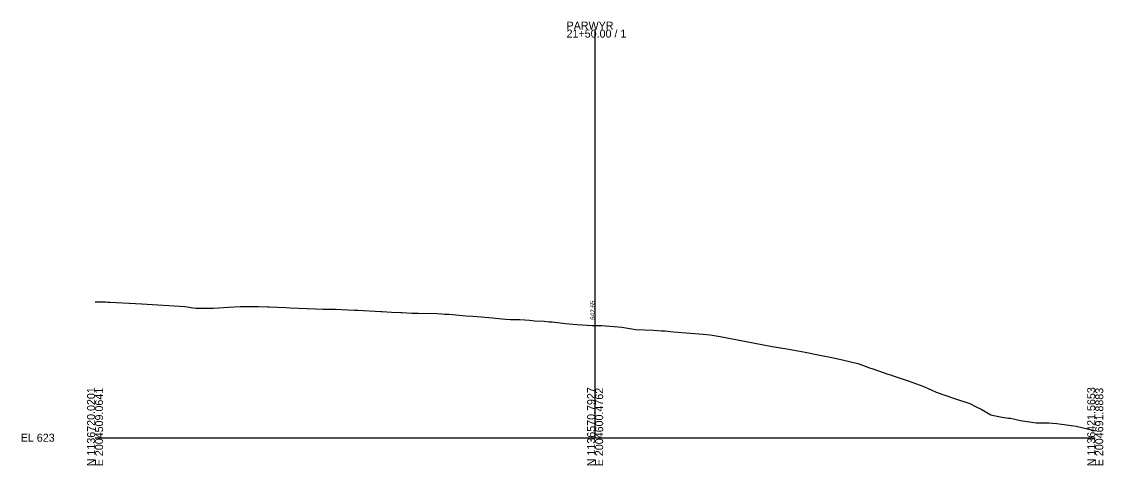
# Model space of a CAD drawing. Extents: x -2173 to 2007764, y -181 to 1138563.
# Drawn here: x -1982.6 to -1604.1, y 2490.3 to 2645.7 of the extents above; entities that cross this region are included whole.
import ezdxf

# ---------------------------------------------------------------- set-up
doc = ezdxf.new("R2010")
doc.units = 0
for name, color, linetype in [('Default', 7, 'Continuous'), ('RD_PD_Final_TrvlWay', 7, 'Continuous'), ('RD_PD_MedBWall', 7, 'Continuous'), ('RD_XS_TX_Elev_EX', 7, 'Continuous')]:
    doc.layers.add(name, color=color, linetype=linetype)

msp = doc.modelspace()

# ---------------------------------------------------------------- linework, layer by layer
at = {"layer": 'RD_PD_Final_TrvlWay'}
msp.add_lwpolyline([(-1956.9, 2547.65), (-1956.16, 2547.63), (-1955.73, 2547.62), (-1955.22, 2547.6), (-1954.01, 2547.58), (-1953.3, 2547.56), (-1952.51, 2547.53), (-1951.6, 2547.49), (-1949.34, 2547.37), (-1944.98, 2547.14), (-1940.57, 2546.89), (-1925.43, 2546), (-1924.65, 2545.88), (-1922.54, 2545.55), (-1921.46, 2545.42), (-1920.51, 2545.35), (-1920.1, 2545.33), (-1919.22, 2545.32), (-1916.69, 2545.36), (-1915.46, 2545.4), (-1910.17, 2545.71), (-1906.12, 2545.91), (-1904.25, 2545.96), (-1902.61, 2545.98), (-1900.04, 2545.92), (-1899.74, 2545.94), (-1896.59, 2545.85), (-1896.01, 2545.83), (-1890.16, 2545.61), (-1888.65, 2545.55), (-1882.65, 2545.3), (-1879.71, 2545.17), (-1877.1, 2545.08), (-1874.89, 2545.03), (-1872.77, 2544.97), (-1868.27, 2544.81), (-1866.16, 2544.72), (-1864.91, 2544.67), (-1856.9, 2544.22), (-1856.46, 2544.2), (-1853.18, 2544), (-1849.91, 2543.84), (-1849.46, 2543.82), (-1846.1, 2543.66), (-1843.81, 2543.59), (-1837.14, 2543.45), (-1835.61, 2543.35), (-1834.49, 2543.26), (-1833, 2543.22), (-1827.1, 2542.74), (-1824.63, 2542.55), (-1817.68, 2542), (-1816.75, 2541.9), (-1813.31, 2541.57), (-1811.51, 2541.44), (-1810.44, 2541.4), (-1808.92, 2541.43), (-1808.2, 2541.35), (-1806.54, 2541.29), (-1804.88, 2541.14), (-1802.96, 2540.96), (-1799.76, 2540.8), (-1797.99, 2540.6), (-1796.97, 2540.54), (-1792.28, 2540), (-1789.61, 2539.76), (-1788.16, 2539.63), (-1782.93, 2539.25), (-1782.61, 2539.28), (-1781.9, 2539.29), (-1781.48, 2539.3), (-1780.64, 2539.28), (-1779.57, 2539.25), (-1778.27, 2539.19), (-1776.78, 2539.1), (-1775.21, 2538.99), (-1773.79, 2538.86), (-1772.54, 2538.7), (-1769.02, 2538.1), (-1768.32, 2538), (-1767.62, 2537.96), (-1761.49, 2537.64), (-1758.73, 2537.47), (-1757.53, 2537.38), (-1754.48, 2537.13), (-1744.06, 2536.23), (-1741.71, 2536), (-1738.15, 2535.42), (-1719.92, 2532), (-1714.88, 2531.08), (-1708.46, 2530), (-1703.26, 2528.92), (-1698.51, 2528), (-1694.84, 2527.18), (-1689.96, 2526), (-1687.11, 2524.99), (-1686.2, 2524.62), (-1684.37, 2524), (-1679.48, 2522.3), (-1678.59, 2522), (-1677.57, 2521.68), (-1672.4, 2519.93), (-1667.21, 2518), (-1664.54, 2516.94), (-1662.57, 2516), (-1656.16, 2513.72), (-1650.81, 2512), (-1648.61, 2510.87), (-1646.83, 2510), (-1643.41, 2508), (-1641.77, 2507.61), (-1639.53, 2507.22), (-1637.23, 2506.89), (-1636.56, 2506.79), (-1633.1, 2506), (-1627.58, 2505.26), (-1626.71, 2505.19), (-1625.89, 2505.18), (-1623.14, 2505.17), (-1621.91, 2505.11), (-1620.36, 2504.99), (-1619.56, 2504.89), (-1613.61, 2504), (-1609.09, 2502.94), (-1606.9, 2502.36)], dxfattribs=at)
at = {"layer": 'RD_PD_MedBWall'}
for p, q in [((-1781.9, 2500), (-1781.9, 2642.94)), ((-1956.9, 2500), (-1781.9, 2500)), ((-1781.9, 2500), (-1606.9, 2500))]:
    msp.add_line(p, q, dxfattribs=at)

# ---------------------------------------------------------------- texts
at = {"layer": 'Default'}
msp.add_text('-', height=0.0001, dxfattribs=at).set_placement((-1956.9, 2500))
at = {"layer": 'RD_PD_MedBWall'}
for s, p in [('21+50.00 / 1', (-1791.9, 2640.14)), ('PARWYR', (-1791.9, 2642.94)), ('EL 623', (-1982.9, 2498.6))]:
    msp.add_text(s, height=2.8, dxfattribs=at).set_placement(p)
for s, p in [('N 1136720.0201', (-1956.9, 2490)), ('E 2004509.0641', (-1954.1, 2490)), ('N 1136570.7927', (-1781.9, 2490)), ('E 2004600.4762', (-1779.1, 2490)), ('N 1136421.5653', (-1606.9, 2490)), ('E 2004691.8883', (-1604.1, 2490))]:
    msp.add_text(s, height=2.8, rotation=90, dxfattribs=at).set_placement(p)
at = {"layer": 'RD_XS_TX_Elev_EX'}
msp.add_text('642.65', height=1.6, rotation=90, dxfattribs=at).set_placement((-1782, 2541.29))

doc.saveas('drawing.dxf')
